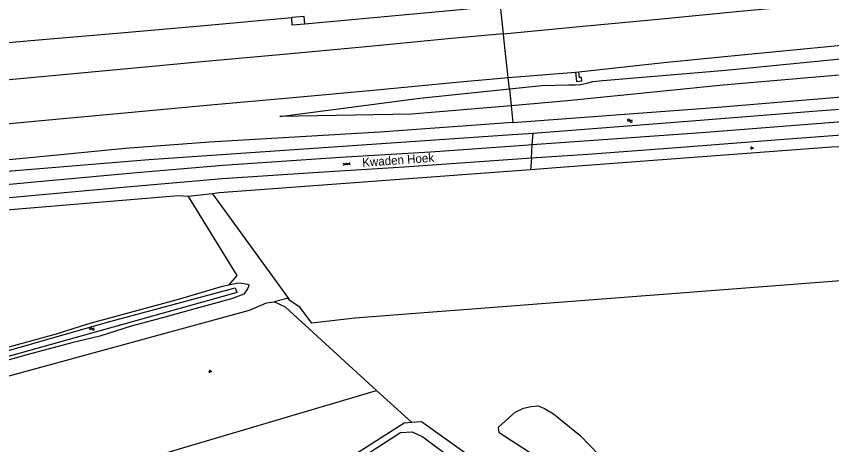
# Model space of a CAD drawing. Extents: x 126000 to 131009, y 393000 to 395500.
# Drawn here: x 129724.5 to 129960.2, y 394437.1 to 394560.9 of the extents above; entities that cross this region are included whole.
import ezdxf

# ---------------------------------------------------------------- set-up
doc = ezdxf.new("R2010")
doc.units = 0
for name, color, linetype in [('gg-anno-openbare ruimte label', 7, 'Continuous'), ('gg-knt-BGT kruinlijn', 7, 'Continuous'), ('gg-knt-verharding', 7, 'Continuous'), ('gg-kntw-bovenkant insteek waterloop', 7, 'Continuous'), ('gg-kntw-waterlijn', 7, 'Continuous'), ('gt-grn-groengrens', 7, 'Continuous'), ('gt-grn-weggrens', 7, 'Continuous'), ('gt-symb-gesloten verharding', 7, 'Continuous'), ('gt-symb-groenvak', 7, 'Continuous'), ('gt-symb-watersymbool', 7, 'Continuous'), ('gx-grn-maaiveld', 7, 'Continuous')]:
    doc.layers.add(name, color=color, linetype=linetype)

# ---------------------------------------------------------------- blocks, each defined once
blk = doc.blocks.new('gt0-GRVAK')
at = {"layer": 'gt-symb-groenvak'}
for p, q in [((-0.11, 0.19), (-0.23, 0.24)), ((-0.18, 0.15), (0.09, 0.15)), ((-0.09, 0.21), (-0.16, 0.32)), ((-0.05, 0.21), (-0.05, 0.39)), ((0, 0.21), (0.06, 0.32)), ((0.01, 0.19), (0.13, 0.24)), ((0.26, -0.05), (0.2, 0.06)), ((0.3, -0.05), (0.3, 0.13)), ((0.35, -0.05), (0.41, 0.06)), ((-0.25, -0.23), (-0.36, -0.18)), ((-0.32, -0.26), (-0.05, -0.26)), ((-0.23, -0.21), (-0.29, -0.1)), ((-0.18, -0.2), (-0.18, -0.02)), ((-0.14, -0.21), (-0.07, -0.1)), ((-0.12, -0.23), (0, -0.18)), ((0.24, -0.07), (0.12, -0.02)), ((0.17, -0.11), (0.44, -0.11)), ((0.37, -0.07), (0.49, -0.02))]:
    blk.add_line(p, q, dxfattribs=at)
blk = doc.blocks.new('gt0-GESVH1')
at = {"layer": 'gt-symb-gesloten verharding'}
for p, q in [((-0.99, -0.26), (0.01, 0.24)), ((0.01, -0.26), (-0.99, 0.24)), ((0.01, 0.24), (1.01, -0.26)), ((1.01, 0.24), (0.01, -0.26))]:
    blk.add_line(p, q, dxfattribs=at)
blk = doc.blocks.new('gt0-WA')
at = {"layer": 'gt-symb-watersymbool'}
for centre, start, end in [((-0.32, 0.02), 28.0725, 151.9275), ((0.43, 0.42), 208.0725, 331.9275), ((-0.32, -0.43), 28.0725, 151.9275), ((0.43, -0.03), 208.0725, 331.9275)]:
    blk.add_arc(centre, 0.425, start, end, dxfattribs=at)

msp = doc.modelspace()

# ---------------------------------------------------------------- linework, layer by layer
at = {"layer": 'gg-knt-BGT kruinlijn'}
for p, q in [((129929.6, 394545.38), (129983.23, 394550.57)), ((129893.99, 394542.4), (129929.6, 394545.38)), ((129867.01, 394539.96), (129876.44, 394540.93)), ((129876.44, 394540.93), (129884.17, 394541.08)), ((129884.17, 394541.08), (129886.01, 394541.15)), ((129886.01, 394541.15), (129887.67, 394541.23)), ((129887.67, 394541.23), (129889.44, 394541.63)), ((129889.44, 394541.63), (129891.11, 394542.02)), ((129891.11, 394542.02), (129893.99, 394542.4)), ((129841.09, 394537.28), (129867.01, 394539.96)), ((129800.61, 394531.92), (129841.09, 394537.28))]:
    msp.add_line(p, q, dxfattribs=at)
msp.add_lwpolyline([(129786.37, 394408.86), (129835.5, 394440.61), (129838.89, 394440.77), (129842.02, 394439.35), (129863.34, 394423.45), (129871.66, 394418.17), (129879.6, 394415.54), (129895.69, 394405.14)], dxfattribs=at)
at = {"layer": 'gg-knt-verharding'}
for points in [[(130020.8, 394535.01), (130001.97, 394533.46), (129975.43, 394531.37), (129949.63, 394529.39), (129923.84, 394527.36), (129898.15, 394525.45), (129873.64, 394523.74)], [(130020.84, 394531.17), (130000, 394529.47), (129973.34, 394527.37), (129945.15, 394525.22), (129916.73, 394522.98), (129889.73, 394521.01), (129873.39, 394519.87)], [(129873.64, 394523.74), (129871.21, 394523.58), (129844.18, 394521.66), (129818.24, 394520.06), (129784.19, 394517.78), (129759.3, 394515.64), (129732.93, 394513.22), (129706.88, 394510.89), (129657.07, 394506.47), (129631.07, 394504.29), (129605.65, 394502.27), (129580.54, 394500.13), (129564.82, 394498.74)], [(129873.39, 394519.87), (129836.6, 394517.3), (129810.32, 394515.65), (129784.11, 394513.89), (129758.59, 394511.72), (129736.18, 394509.71), (129685.62, 394505.1), (129660.98, 394503.02), (129635.31, 394500.73), (129608.05, 394498.61), (129566.02, 394494.97)]]:
    msp.add_lwpolyline(points, dxfattribs=at)
at = {"layer": 'gg-kntw-bovenkant insteek waterloop'}
for points in [[(129873.86, 394527.18), (129918.51, 394530.59), (129956.01, 394533.55), (130000, 394536.79)], [(129600.28, 394505.58), (129707.76, 394514.95), (129762.81, 394519.5), (129866.46, 394526.61), (129873.86, 394527.18)]]:
    msp.add_lwpolyline(points, dxfattribs=at)
at = {"layer": 'gg-kntw-waterlijn'}
msp.add_line((129786.55, 394480.58), (129708.55, 394458.81), dxfattribs=at)
msp.add_lwpolyline([(129685.28, 394452.43), (129707.94, 394460.27), (129750.46, 394472.39), (129787.74, 394482.46), (129788.27, 394481.07), (129786.55, 394480.58)], dxfattribs=at)
at = {"layer": 'gt-grn-groengrens'}
for p, q in [((129873.64, 394523.74), (129873.86, 394527.18)), ((129873.39, 394519.87), (129873.17, 394516.55))]:
    msp.add_line(p, q, dxfattribs=at)
for points in [[(129807.04, 394424.55), (129836.65, 394443.43), (129838.68, 394443.59)], [(129838.68, 394443.59), (129841.62, 394443.83), (129895.69, 394405.14)]]:
    msp.add_lwpolyline(points, dxfattribs=at)
at = {"layer": 'gt-grn-weggrens'}
msp.add_line((129873.39, 394519.87), (129873.64, 394523.74), dxfattribs=at)
at = {"layer": 'gx-grn-maaiveld'}
for p, q in [((129865.31, 394555.86), (129864.45, 394563.96)), ((129866.66, 394543.23), (129886.09, 394544.73)), ((129867.01, 394539.96), (129866.66, 394543.23)), ((129886.09, 394544.73), (129887.12, 394544.86)), ((129867.01, 394539.96), (129867.53, 394535.05)), ((129867.53, 394535.05), (129868.05, 394530.23)), ((129781.17, 394509.61), (129774.16, 394508.87)), ((129781.17, 394509.61), (129803.13, 394479.35)), ((129764.79, 394433.89), (129828.65, 394452.73)), ((129838.68, 394443.59), (129828.65, 394452.73))]:
    msp.add_line(p, q, dxfattribs=at)
for points in [[(129865.31, 394555.86), (129886.19, 394557.85), (129910.03, 394560.07), (129933.68, 394562.39), (129956.97, 394564.55), (129980.82, 394566.91), (130000, 394568.83), (130016.81, 394570.43), (130044.1, 394573.04), (130072.01, 394575.76), (130083.66, 394576.9), (130097.65, 394578.25), (130110.96, 394579.54), (130133.43, 394581.78), (130163.47, 394584.66), (130173.66, 394585.64), (130195.51, 394587.72), (130221.22, 394590.07), (130241.6, 394591.94), (130243.59, 394592.11)], [(129887.12, 394544.86), (129911.69, 394547.54), (129935.12, 394549.89), (129959.1, 394552.19), (129982.55, 394554.48), (130000, 394555.9), (130018.99, 394557.82), (130042.83, 394560.22), (130070.58, 394562.88), (130084.7, 394564.28), (130102.48, 394566.02), (130124.5, 394568.19), (130131.03, 394568.83), (130137.15, 394569.43), (130148.28, 394570.48), (130163.24, 394571.88), (130175.23, 394573.07), (130188.26, 394574.35), (130211.58, 394576.55), (130224.51, 394577.78), (130238.97, 394579.09), (130241, 394579.29), (130244.5, 394579.57)], [(129864.45, 394563.96), (129850.87, 394562.63), (129826.7, 394560.34), (129807.93, 394558.66)], [(130244.98, 394562.83), (130222.44, 394561.24), (130200.13, 394559.72), (130178.68, 394558.24), (130130.35, 394554.59), (130081.68, 394550.13), (130032.22, 394547.28), (130000, 394546.09), (129977.98, 394545.27), (129928.85, 394541), (129883.83, 394536.45), (129867.53, 394535.05)], [(129490.41, 394532.95), (129515.68, 394535.26), (129539.55, 394537.23), (129563.35, 394539.26), (129587.5, 394541.49), (129611.29, 394543.49), (129635.23, 394545.73), (129659.25, 394547.77), (129682.95, 394549.87), (129706.9, 394551.99), (129730.93, 394554.13), (129754.65, 394556.18), (129778.77, 394558.3), (129804.09, 394560.55)], [(129807.93, 394558.66), (129807.66, 394560.9), (129804.09, 394560.55)], [(129807.93, 394558.66), (129804.19, 394558.37), (129804.09, 394560.55)], [(129865.31, 394555.86), (129850.33, 394554.46), (129826.6, 394552.21), (129802.81, 394549.97), (129779.17, 394547.81), (129755.54, 394545.62), (129731.72, 394543.4), (129707.93, 394541.18), (129684.07, 394538.96), (129660.51, 394536.78), (129636.62, 394534.63), (129613.04, 394532.48), (129589.25, 394530.34), (129565.21, 394528.16), (129541.7, 394526.15), (129517.59, 394523.97), (129491.27, 394521.64)], [(129866.66, 394543.23), (129866.2, 394547.52), (129865.82, 394551.06), (129865.44, 394554.67), (129865.31, 394555.86)], [(129492.23, 394509.09), (129518.53, 394511.47), (129543.02, 394513.62), (129567.43, 394515.8), (129590.31, 394517.93), (129614.37, 394520.05), (129637.78, 394522.25), (129661.62, 394524.37), (129685.68, 394526.47), (129709.24, 394528.71), (129732.82, 394530.9), (129756.85, 394533.14), (129780.62, 394535.31), (129804.43, 394537.49), (129827.65, 394539.52), (129851.77, 394541.91), (129866.66, 394543.23)], [(129886.09, 394544.73), (129886.41, 394542.04), (129887.96, 394542.26), (129887.87, 394543.27), (129887.28, 394543.2), (129887.12, 394544.86)], [(129868.05, 394530.23), (129924.94, 394534.44), (130000, 394540.67)], [(129867.53, 394535.05), (129838.72, 394532.59), (129800.61, 394531.92)], [(129868.05, 394530.23), (129829.6, 394527.45), (129780.31, 394524.49), (129755.99, 394522.74), (129729.44, 394520.13), (129704.92, 394517.82), (129682.85, 394515.82), (129667.66, 394514.54), (129656.34, 394513.59), (129609.99, 394509.66), (129600.04, 394508.83)], [(129962.82, 394523.19), (129960.19, 394523.12), (129933.05, 394521.03), (129883.09, 394517.28), (129873.17, 394516.55)], [(129873.17, 394516.55), (129783.12, 394509.93), (129781.17, 394509.61)], [(129774.16, 394508.87), (129771.33, 394509.01), (129714.65, 394504.34), (129674.72, 394500.32)], [(129774.16, 394508.87), (129788.18, 394486.02), (129785.96, 394483.29)], [(130002.93, 394488.06), (129991.71, 394486.65), (129822.33, 394473.63), (129809.95, 394472.23), (129806.51, 394476.73), (129803.54, 394478.79), (129803.13, 394479.35)], [(129785.96, 394483.29), (129788.6, 394483.84), (129789.66, 394483.81), (129791.28, 394483.49), (129791.65, 394483.25), (129791.61, 394482.82), (129791.31, 394482.12), (129790.25, 394480.63), (129786.73, 394479.26), (129776.07, 394476.36), (129766.74, 394473.78), (129757.71, 394471.31), (129748.59, 394468.47), (129740.5, 394466.56), (129727.86, 394463.17), (129718.95, 394460.62), (129711.87, 394458.41), (129707.49, 394456.91)], [(129601.62, 394424.56), (129603.12, 394425.09), (129612.8, 394428.46), (129617.89, 394430.23), (129626.68, 394433.51), (129639.83, 394437.99), (129650.9, 394442.07), (129663.87, 394446.52), (129676.74, 394451.21), (129687.18, 394454.47), (129698.05, 394457.7), (129702.27, 394459.17), (129707.22, 394460.83), (129716.66, 394463.79), (129736.05, 394469.1), (129745.13, 394472.03), (129771.77, 394479.23), (129784.05, 394482.9), (129785.96, 394483.29)], [(129803.13, 394479.35), (129802.8, 394479.38), (129799.04, 394478.39)], [(129724.76, 394421.98), (129719.05, 394430.94), (129709.62, 394453.54), (129791.92, 394475.92), (129796.8, 394478.12), (129799.04, 394478.39)], [(129828.65, 394452.73), (129802.25, 394476.8), (129799.04, 394478.39)], [(129873.31, 394448.08), (129875.3, 394448.34), (129877.15, 394447.55), (129879.8, 394445.96), (129887.47, 394439.74), (129896.07, 394430.88), (129896.99, 394429.29), (129897.26, 394426.78), (129897.39, 394425.33), (129896.47, 394423.21), (129895.14, 394421.75), (129893.69, 394421.36), (129864.05, 394440.54), (129863.88, 394442.18), (129868.68, 394446.49), (129871.07, 394447.68), (129873.31, 394448.08)]]:
    msp.add_lwpolyline(points, dxfattribs=at)

# ---------------------------------------------------------------- block references
at = {"layer": 'gt-symb-gesloten verharding', "rotation": 5.334440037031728}
msp.add_blockref('gt0-GESVH1', (129819.96, 394518.22), dxfattribs=at)
at = {"layer": 'gt-symb-groenvak'}
for p in [(129937.11, 394522.87), (129780.49, 394458.33)]:
    msp.add_blockref('gt0-GRVAK', p, dxfattribs=at)
at = {"layer": 'gt-symb-watersymbool'}
for p, rotation in [((129901.8, 394530.73), 5.163306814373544), ((129746.26, 394470.56), 16.079172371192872)]:
    msp.add_blockref('gt0-WA', p, dxfattribs=dict(at, rotation=rotation))

# ---------------------------------------------------------------- texts
at = {"layer": 'gg-anno-openbare ruimte label'}
msp.add_text('Kwaden Hoek', height=2.5, rotation=4, dxfattribs=at).set_placement((129824.56, 394517.4))

doc.saveas('drawing.dxf')
